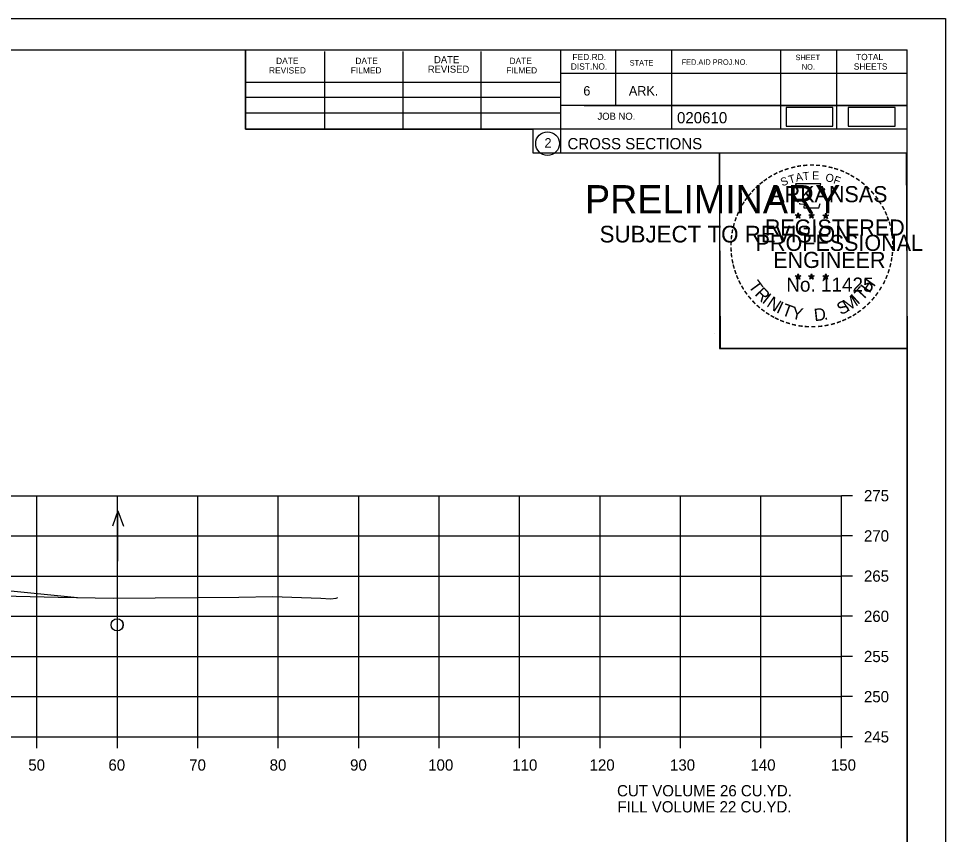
# Model space of a CAD drawing. Extents: x 1103485 to 1107180, y 2010593 to 2011873.
# Drawn here: x 1107064.9 to 1107180.1, y 2011131.3 to 2011232.8 of the extents above; entities that cross this region are included whole.
import ezdxf

# ---------------------------------------------------------------- set-up
doc = ezdxf.new("R2010")
doc.units = 0
for name, color, linetype in [('R_Axis', 7, 'Continuous'), ('R_Axis Annot', 7, 'Continuous'), ('R_Border', 7, 'Continuous'), ('R_Border PE', 7, 'Continuous'), ('R_Border Prem', 7, 'Continuous'), ('R_Drive', 7, 'Continuous'), ('R_Exist Surface', 7, 'Continuous'), ('R_Grid', 7, 'Continuous'), ('R_No Plot', 7, 'Continuous'), ('R_Water', 7, 'Continuous'), ('R_Water Annot', 7, 'Continuous')]:
    doc.layers.add(name, color=color, linetype=linetype)

msp = doc.modelspace()

# ---------------------------------------------------------------- linework, layer by layer
at = {"layer": 'R_Axis'}
for p, q in [((1107167.18, 2011143.49), (1107167.18, 2011173.49)), ((1107168.58, 2011173.49), (1107167.18, 2011173.49)), ((1107168.58, 2011168.49), (1107167.18, 2011168.49)), ((1107168.58, 2011163.49), (1107167.18, 2011163.49)), ((1107168.58, 2011158.49), (1107167.18, 2011158.49)), ((1107168.58, 2011153.49), (1107167.18, 2011153.49)), ((1107168.58, 2011148.49), (1107167.18, 2011148.49)), ((1106867.18, 2011143.49), (1107167.18, 2011143.49)), ((1107067.18, 2011142.09), (1107067.18, 2011143.49)), ((1107077.18, 2011142.09), (1107077.18, 2011143.49)), ((1107087.18, 2011142.09), (1107087.18, 2011143.49)), ((1107097.18, 2011142.09), (1107097.18, 2011143.49)), ((1107107.18, 2011142.09), (1107107.18, 2011143.49)), ((1107117.18, 2011142.09), (1107117.18, 2011143.49)), ((1107127.18, 2011142.09), (1107127.18, 2011143.49)), ((1107137.18, 2011142.09), (1107137.18, 2011143.49)), ((1107147.18, 2011142.09), (1107147.18, 2011143.49)), ((1107157.18, 2011142.09), (1107157.18, 2011143.49)), ((1107167.18, 2011142.09), (1107167.18, 2011143.49)), ((1107168.58, 2011143.49), (1107167.18, 2011143.49))]:
    msp.add_line(p, q, dxfattribs=at)
at = {"layer": 'R_Border'}
for p, q in [((1106859.18, 2011228.95), (1107175.36, 2011228.95)), ((1107093.1, 2011219.07), (1107093.1, 2011228.95)), ((1107102.96, 2011219.07), (1107102.96, 2011228.75)), ((1107112.72, 2011219.07), (1107112.72, 2011228.75)), ((1107122.4, 2011219.07), (1107122.4, 2011228.75)), ((1107132.26, 2011228.95), (1107132.26, 2011216.15)), ((1107139.1, 2011228.95), (1107139.1, 2011222.01)), ((1107146.04, 2011228.95), (1107146.04, 2011219.07)), ((1107159.62, 2011228.95), (1107159.62, 2011219.07)), ((1107166.56, 2011228.95), (1107166.56, 2011219.07)), ((1107175.36, 2011023.49), (1107175.36, 2011228.95)), ((1107175.36, 2011226.01), (1107132.26, 2011226.01)), ((1107175.36, 2011226.03), (1107175.36, 2011226.03)), ((1107093.1, 2011224.93), (1107132.26, 2011224.93)), ((1107093.1, 2011223.07), (1107132.26, 2011223.07)), ((1107175.36, 2011222.01), (1107132.26, 2011222.01)), ((1107135.22, 2011222.01), (1107175.36, 2011222.01)), ((1107093.1, 2011219.07), (1107093.1, 2011221.13)), ((1107093.1, 2011221.13), (1107132.26, 2011221.13)), ((1107175.36, 2011219.07), (1107093.1, 2011219.07)), ((1107132.26, 2011216.15), (1107175.36, 2011216.15))]:
    msp.add_line(p, q, dxfattribs=at)
msp.add_circle((1107130.65, 2011217.29), 1.47, dxfattribs=at)
at = {"layer": 'R_Border PE'}
for p, q in [((1107161.45, 2011208.41), (1107161.8, 2011208.3)), ((1107161.45, 2011208.41), (1107161.7, 2011208.36)), ((1107161.45, 2011208.41), (1107161.69, 2011208.29)), ((1107161.58, 2011208), (1107161.8, 2011208.3)), ((1107161.58, 2011208), (1107161.71, 2011208.24)), ((1107161.58, 2011208), (1107161.8, 2011208.22)), ((1107161.8, 2011208.66), (1107161.76, 2011208.41)), ((1107161.8, 2011208.3), (1107161.8, 2011208.66)), ((1107161.8, 2011208.66), (1107161.85, 2011208.41)), ((1107162.14, 2011208.41), (1107161.8, 2011208.3)), ((1107162.01, 2011208), (1107161.8, 2011208.3)), ((1107162.01, 2011208), (1107161.8, 2011208.21)), ((1107162.14, 2011208.41), (1107161.86, 2011208.36)), ((1107162.01, 2011208), (1107161.87, 2011208.29)), ((1107162.14, 2011208.41), (1107161.94, 2011208.31)), ((1107163.12, 2011208.41), (1107163.47, 2011208.3)), ((1107163.12, 2011208.41), (1107163.37, 2011208.36)), ((1107163.12, 2011208.41), (1107163.36, 2011208.29)), ((1107163.25, 2011208), (1107163.47, 2011208.3)), ((1107163.25, 2011208), (1107163.38, 2011208.24)), ((1107163.25, 2011208), (1107163.47, 2011208.22)), ((1107163.47, 2011208.66), (1107163.43, 2011208.41)), ((1107163.47, 2011208.3), (1107163.47, 2011208.66)), ((1107163.47, 2011208.66), (1107163.52, 2011208.41)), ((1107163.81, 2011208.41), (1107163.47, 2011208.3)), ((1107163.68, 2011208), (1107163.47, 2011208.3)), ((1107163.68, 2011208), (1107163.47, 2011208.21)), ((1107163.81, 2011208.41), (1107163.53, 2011208.36)), ((1107163.68, 2011208), (1107163.54, 2011208.29)), ((1107163.81, 2011208.41), (1107163.61, 2011208.31)), ((1107164.88, 2011208.4), (1107165.23, 2011208.28)), ((1107164.88, 2011208.4), (1107165.14, 2011208.35)), ((1107164.88, 2011208.4), (1107165.12, 2011208.27)), ((1107165.02, 2011207.99), (1107165.23, 2011208.28)), ((1107165.02, 2011207.99), (1107165.14, 2011208.23)), ((1107165.02, 2011207.99), (1107165.23, 2011208.2)), ((1107165.23, 2011208.65), (1107165.19, 2011208.4)), ((1107165.23, 2011208.28), (1107165.23, 2011208.65)), ((1107165.23, 2011208.65), (1107165.28, 2011208.4)), ((1107165.58, 2011208.4), (1107165.23, 2011208.28)), ((1107165.44, 2011207.99), (1107165.23, 2011208.28)), ((1107165.44, 2011207.99), (1107165.23, 2011208.2)), ((1107165.58, 2011208.4), (1107165.29, 2011208.35)), ((1107165.44, 2011207.99), (1107165.31, 2011208.28)), ((1107165.58, 2011208.4), (1107165.37, 2011208.29)), ((1107161.44, 2011200.83), (1107161.79, 2011200.72)), ((1107161.44, 2011200.83), (1107161.7, 2011200.79)), ((1107161.44, 2011200.83), (1107161.68, 2011200.71)), ((1107161.58, 2011200.43), (1107161.79, 2011200.72)), ((1107161.58, 2011200.43), (1107161.7, 2011200.67)), ((1107161.58, 2011200.43), (1107161.79, 2011200.64)), ((1107161.79, 2011201.09), (1107161.75, 2011200.84)), ((1107161.79, 2011200.72), (1107161.79, 2011201.09)), ((1107161.79, 2011201.09), (1107161.84, 2011200.84)), ((1107162.14, 2011200.83), (1107161.79, 2011200.72)), ((1107162.01, 2011200.43), (1107161.79, 2011200.72)), ((1107162.01, 2011200.43), (1107161.79, 2011200.64)), ((1107162.14, 2011200.83), (1107161.85, 2011200.79)), ((1107162.01, 2011200.43), (1107161.87, 2011200.72)), ((1107162.14, 2011200.83), (1107161.94, 2011200.73)), ((1107163.11, 2011200.83), (1107163.46, 2011200.72)), ((1107163.11, 2011200.83), (1107163.37, 2011200.79)), ((1107163.11, 2011200.83), (1107163.35, 2011200.71)), ((1107163.25, 2011200.43), (1107163.46, 2011200.72)), ((1107163.25, 2011200.43), (1107163.37, 2011200.67)), ((1107163.25, 2011200.43), (1107163.46, 2011200.64)), ((1107163.46, 2011201.09), (1107163.42, 2011200.84)), ((1107163.46, 2011200.72), (1107163.46, 2011201.09)), ((1107163.46, 2011201.09), (1107163.51, 2011200.84)), ((1107163.81, 2011200.83), (1107163.46, 2011200.72)), ((1107163.68, 2011200.43), (1107163.46, 2011200.72)), ((1107163.68, 2011200.43), (1107163.46, 2011200.64)), ((1107163.81, 2011200.83), (1107163.52, 2011200.79)), ((1107163.68, 2011200.43), (1107163.54, 2011200.72)), ((1107163.81, 2011200.83), (1107163.61, 2011200.73)), ((1107164.88, 2011200.82), (1107165.23, 2011200.71)), ((1107164.88, 2011200.82), (1107165.13, 2011200.78)), ((1107164.88, 2011200.82), (1107165.12, 2011200.7)), ((1107165.01, 2011200.42), (1107165.23, 2011200.71)), ((1107165.01, 2011200.42), (1107165.14, 2011200.66)), ((1107165.01, 2011200.42), (1107165.23, 2011200.63)), ((1107165.23, 2011201.08), (1107165.19, 2011200.83)), ((1107165.23, 2011200.71), (1107165.23, 2011201.08)), ((1107165.23, 2011201.08), (1107165.28, 2011200.83)), ((1107165.58, 2011200.82), (1107165.23, 2011200.71)), ((1107165.44, 2011200.42), (1107165.23, 2011200.71)), ((1107165.44, 2011200.42), (1107165.23, 2011200.63)), ((1107165.58, 2011200.82), (1107165.29, 2011200.78)), ((1107165.44, 2011200.42), (1107165.31, 2011200.71)), ((1107165.58, 2011200.82), (1107165.37, 2011200.72))]:
    msp.add_line(p, q, dxfattribs=at)
for points in [[(1107161.49, 2011212.29), (1107161.76, 2011211.46)], [(1107165, 2011211.36), (1107165.14, 2011211.65), (1107164.46, 2011211.62), (1107164.61, 2011212.29), (1107161.49, 2011212.29)], [(1107161.98, 2011209.86), (1107161.98, 2011209.78), (1107162.54, 2011209.76), (1107162.49, 2011209.28), (1107164.36, 2011209.28), (1107164.56, 2011209.82)], [(1107161.8, 2011208.66), (1107162.01, 2011208), (1107161.45, 2011208.41), (1107162.14, 2011208.41), (1107161.58, 2011208), (1107161.8, 2011208.66)], [(1107163.47, 2011208.66), (1107163.68, 2011208), (1107163.12, 2011208.41), (1107163.81, 2011208.41), (1107163.25, 2011208), (1107163.47, 2011208.66)], [(1107165.23, 2011208.65), (1107165.44, 2011207.99), (1107164.88, 2011208.4), (1107165.58, 2011208.4), (1107165.02, 2011207.99), (1107165.23, 2011208.65)], [(1107161.79, 2011201.09), (1107162.01, 2011200.43), (1107161.44, 2011200.83), (1107162.14, 2011200.83), (1107161.58, 2011200.43), (1107161.79, 2011201.09)], [(1107163.46, 2011201.09), (1107163.68, 2011200.43), (1107163.11, 2011200.83), (1107163.81, 2011200.83), (1107163.25, 2011200.43), (1107163.46, 2011201.09)], [(1107165.23, 2011201.08), (1107165.44, 2011200.42), (1107164.88, 2011200.82), (1107165.58, 2011200.82), (1107165.01, 2011200.42), (1107165.23, 2011201.08)]]:
    msp.add_lwpolyline(points, dxfattribs=at)
for centre, radius in [((1107161.8, 2011208.3), 0.172), ((1107161.8, 2011208.3), 0.145), ((1107161.8, 2011208.3), 0.116), ((1107161.8, 2011208.3), 0.0991), ((1107161.8, 2011208.3), 0.0747), ((1107161.8, 2011208.3), 0.0495), ((1107161.8, 2011208.3), 0.0296), ((1107163.47, 2011208.3), 0.172), ((1107163.47, 2011208.3), 0.145), ((1107163.47, 2011208.3), 0.116), ((1107163.47, 2011208.3), 0.0991), ((1107163.47, 2011208.3), 0.0747), ((1107163.47, 2011208.3), 0.0495), ((1107163.47, 2011208.3), 0.0296), ((1107165.23, 2011208.28), 0.172), ((1107165.23, 2011208.28), 0.145), ((1107165.23, 2011208.28), 0.116), ((1107165.23, 2011208.28), 0.0991), ((1107165.23, 2011208.28), 0.0747), ((1107165.23, 2011208.28), 0.0495), ((1107165.23, 2011208.28), 0.0296), ((1107161.79, 2011200.72), 0.172), ((1107161.79, 2011200.72), 0.145), ((1107161.79, 2011200.72), 0.116), ((1107161.79, 2011200.72), 0.0991), ((1107161.79, 2011200.72), 0.0747), ((1107161.79, 2011200.72), 0.0495), ((1107161.79, 2011200.72), 0.0296), ((1107163.46, 2011200.72), 0.172), ((1107163.46, 2011200.72), 0.145), ((1107163.46, 2011200.72), 0.116), ((1107163.46, 2011200.72), 0.0991), ((1107163.46, 2011200.72), 0.0747), ((1107163.46, 2011200.72), 0.0495), ((1107163.46, 2011200.72), 0.0296), ((1107165.23, 2011200.71), 0.172), ((1107165.23, 2011200.71), 0.145), ((1107165.23, 2011200.71), 0.116), ((1107165.23, 2011200.71), 0.0991), ((1107165.23, 2011200.71), 0.0747), ((1107165.23, 2011200.71), 0.0495), ((1107165.23, 2011200.71), 0.0296)]:
    msp.add_circle(centre, radius, dxfattribs=at)
at = {"layer": 'R_Drive'}
msp.add_line((1107048.15, 2011163.24), (1107072.23, 2011160.83), dxfattribs=at)
at = {"layer": 'R_Exist Surface'}
msp.add_lwpolyline([(1107061.07, 2011161.07), (1107069.8, 2011160.88), (1107076.69, 2011160.74), (1107092.27, 2011160.88), (1107096.46, 2011160.97), (1107102.47, 2011160.74), (1107103.68, 2011160.68), (1107104.37, 2011160.73), (1107104.56, 2011160.83)], dxfattribs=at)
at = {"layer": 'R_Grid'}
for p, q in [((1106867.18, 2011173.49), (1107167.18, 2011173.49)), ((1107067.18, 2011143.49), (1107067.18, 2011173.49)), ((1107077.18, 2011143.49), (1107077.18, 2011173.49)), ((1107087.18, 2011143.49), (1107087.18, 2011173.49)), ((1107097.18, 2011143.49), (1107097.18, 2011173.49)), ((1107107.18, 2011143.49), (1107107.18, 2011173.49)), ((1107117.18, 2011143.49), (1107117.18, 2011173.49)), ((1107127.18, 2011143.49), (1107127.18, 2011173.49)), ((1107137.18, 2011143.49), (1107137.18, 2011173.49)), ((1107147.18, 2011143.49), (1107147.18, 2011173.49)), ((1107157.18, 2011143.49), (1107157.18, 2011173.49)), ((1107167.18, 2011143.49), (1107167.18, 2011173.49)), ((1106867.18, 2011168.49), (1107167.18, 2011168.49)), ((1106867.18, 2011163.49), (1107167.18, 2011163.49)), ((1106867.18, 2011158.49), (1107167.18, 2011158.49)), ((1106867.18, 2011153.49), (1107167.18, 2011153.49)), ((1106867.18, 2011148.49), (1107167.18, 2011148.49)), ((1106867.18, 2011143.49), (1107167.18, 2011143.49))]:
    msp.add_line(p, q, dxfattribs=at)
at = {"layer": 'R_No Plot'}
for p, q in [((1106846.78, 2011232.85), (1107180.12, 2011232.85)), ((1107151.4, 2011193.7), (1107151.4, 2011193.7))]:
    msp.add_line(p, q, dxfattribs=at)
for points in [[(1106846.78, 2011232.85), (1107180.12, 2011232.85), (1107180.12, 2011019.51), (1106846.78, 2011019.51)], [(1107093.1, 2011228.95), (1107093.1, 2011219.07), (1107128.84, 2011219.07), (1107128.84, 2011216.15), (1107152.04, 2011216.15), (1107152.04, 2011191.82), (1107175.36, 2011191.82), (1107175.36, 2011023.49), (1106859.18, 2011023.49), (1106859.18, 2011228.95)], [(1107152.04, 2011216.15), (1107175.24, 2011216.15), (1107175.36, 2011191.82), (1107152.16, 2011191.82)]]:
    msp.add_lwpolyline(points, close=True, dxfattribs=at)
at = {"layer": 'R_Water'}
for points in [[(1107160.3, 2011219.47), (1107166.13, 2011219.47), (1107166.13, 2011221.78), (1107160.3, 2011221.78)], [(1107168.04, 2011219.45), (1107173.87, 2011219.45), (1107173.87, 2011221.76), (1107168.04, 2011221.76)]]:
    msp.add_lwpolyline(points, close=True, dxfattribs=at)
for radius in [0.755, 0.75]:
    msp.add_circle((1107077.14, 2011157.42), radius, dxfattribs=at)
at = {"layer": 'R_Water Annot'}
for p, q in [((1107077.25, 2011171.61), (1107076.55, 2011169.69)), ((1107077.25, 2011165.33), (1107077.25, 2011171.61)), ((1107077.25, 2011171.61), (1107077.95, 2011169.69))]:
    msp.add_line(p, q, dxfattribs=at)

# ---------------------------------------------------------------- texts
at = {"layer": 'R_Axis Annot'}
for s, p in [('275', (1107169.98, 2011172.79)), ('270', (1107169.98, 2011167.79)), ('265', (1107169.98, 2011162.79)), ('260', (1107169.98, 2011157.79)), ('255', (1107169.98, 2011152.79)), ('250', (1107169.98, 2011147.79)), ('245', (1107169.98, 2011142.79)), ('50', (1107066.1, 2011139.29)), ('60', (1107076.06, 2011139.29)), ('70', (1107086.1, 2011139.29)), ('80', (1107096.1, 2011139.29)), ('90', (1107106.1, 2011139.29)), ('100', (1107115.81, 2011139.29)), ('110', (1107126.26, 2011139.29)), ('120', (1107135.87, 2011139.29)), ('130', (1107145.87, 2011139.29)), ('140', (1107155.87, 2011139.29)), ('150', (1107165.87, 2011139.29)), ('CUT VOLUME 26 CU.YD.', (1107139.29, 2011136.09)), ('FILL VOLUME 22 CU.YD.', (1107139.34, 2011134.09))]:
    msp.add_text(s, height=1.4, dxfattribs=at).set_placement(p)
at = {"layer": 'R_Border'}
for s, height, p in [('FED.RD.', 0.782, (1107133.74, 2011227.67)), ('SHEET', 0.684, (1107161.48, 2011227.67)), ('TOTAL', 0.782, (1107169, 2011227.67)), ('DATE', 0.782, (1107096.9, 2011227.19)), ('DATE', 0.782, (1107106.76, 2011227.19)), ('DATE', 0.879, (1107116.54, 2011227.29)), ('DATE', 0.782, (1107125.92, 2011227.19)), ('DIST.NO.', 0.782, (1107133.54, 2011226.49)), ('STATE', 0.684, (1107140.86, 2011226.99)), ('FED.AID PROJ.NO.', 0.684, (1107147.32, 2011227.09)), ('NO.', 0.684, (1107162.26, 2011226.49)), ('SHEETS', 0.782, (1107168.72, 2011226.49)), ('REVISED', 0.782, (1107096.02, 2011226.01)), ('FILMED', 0.782, (1107106.18, 2011226.01)), ('REVISED', 0.879, (1107115.76, 2011226.11)), ('FILMED', 0.782, (1107125.52, 2011226.01)), ('6', 1.17, (1107135.1, 2011223.27)), ('ARK.', 1.172, (1107140.76, 2011223.27)), ('JOB NO.', 0.879, (1107136.86, 2011220.25)), ('020610', 1.4, (1107146.74, 2011219.81)), ('2', 1.17, (1107130.27, 2011216.8)), ('CROSS SECTIONS', 1.4, (1107133.13, 2011216.58))]:
    msp.add_text(s, height=height, rotation=360, dxfattribs=at).set_placement(p)
at = {"layer": 'R_Border PE'}
for s, height, rotation, p in [('-', 1.6, 13.6301, (1107160.99, 2011213.65)), ('-', 1.6, 10.2193, (1107161.67, 2011213.82)), ('-', 1.6, 5.8968, (1107162.39, 2011213.93)), ('-', 1.6, 0.1862, (1107163.17, 2011214)), ('-', 1.6, 357.743, (1107163.89, 2011213.98)), ('-', 1.6, 352.1617, (1107164.63, 2011213.93)), ('-', 1.6, 347.2049, (1107165.35, 2011213.81)), ('-', 1.6, 34.0636, (1107158.37, 2011212.46)), ('-', 1.6, 28.7918, (1107158.97, 2011212.83)), ('-', 1.6, 24.3072, (1107159.6, 2011213.14)), ('-', 1.6, 19.1761, (1107160.24, 2011213.41)), ('T', 1, 16.4036, (1107160.76, 2011212.29)), ('A', 1, 11.2132, (1107161.58, 2011212.55)), ('T', 1, 6.0228, (1107162.43, 2011212.71)), ('E', 1, 0.8323, (1107163.54, 2011212.82)), ('O', 1, 350.4515, (1107165.14, 2011212.61)), ('-', 1.6, 342.3362, (1107165.99, 2011213.66)), ('-', 1.6, 337.8551, (1107166.72, 2011213.44)), ('-', 1.6, 334.1211, (1107167.35, 2011213.17)), ('-', 1.6, 329.6409, (1107167.93, 2011212.88)), ('-', 1.6, 42.9622, (1107156.89, 2011211.27)), ('-', 1.6, 38.9507, (1107157.32, 2011211.68)), ('-', 1.6, 36.2317, (1107157.8, 2011212.06)), ('S', 1, 21.594, (1107159.84, 2011211.96)), ('F', 1, 340.0707, (1107166.1, 2011212.38)), ('-', 1.6, 325.8627, (1107168.58, 2011212.52)), ('-', 1.6, 320.5297, (1107169.19, 2011212.1)), ('-', 1.6, 50.6142, (1107156.04, 2011210.3)), ('-', 1.6, 48.423, (1107156.44, 2011210.79)), ('ARKANSAS', 2, 360, (1107158.34, 2011210)), ('-', 1.6, 315.5786, (1107169.78, 2011211.61)), ('-', 1.6, 309.8797, (1107170.35, 2011211.06)), ('-', 1.6, 58.0706, (1107155.3, 2011209.21)), ('-', 1.6, 54.2325, (1107155.62, 2011209.74)), ('-', 1.6, 306.6522, (1107170.88, 2011210.46)), ('-', 1.4, 303.6753, (1107171.36, 2011209.89)), ('-', 1.6, 67.7743, (1107154.73, 2011207.98)), ('-', 1.6, 62.8713, (1107154.98, 2011208.59)), ('-', 1.6, 299.6684, (1107171.68, 2011209.28)), ('-', 1.6, 294.6628, (1107172.01, 2011208.67)), ('-', 1.6, 72.3945, (1107154.51, 2011207.35)), ('REGISTERED', 2, 360, (1107157.66, 2011205.85)), ('DWB', 0.01, 360, (1107161.78, 2011208.29)), ('DWB', 0.01, 360, (1107163.45, 2011208.29)), ('DWB', 0.01, 360, (1107165.22, 2011208.28)), ('-', 1.6, 290.5728, (1107172.26, 2011208.09)), ('-', 1.6, 285.1233, (1107172.5, 2011207.51)), ('-', 1.6, 81.2013, (1107154.18, 2011205.93)), ('-', 1.6, 75.461, (1107154.31, 2011206.64)), ('-', 1.6, 280.5493, (1107172.7, 2011206.77)), ('-', 1.6, 85.1863, (1107154.1, 2011205.24)), ('PROFESSIONAL', 2, 360, (1107156.52, 2011203.94)), ('-', 1.6, 276.5962, (1107172.86, 2011206)), ('-', 1.6, 274.3301, (1107172.92, 2011205.28)), ('-', 1.6, 94.1959, (1107154.11, 2011203.81)), ('-', 1.6, 89.0622, (1107154.08, 2011204.53)), ('-', 1.6, 269.9407, (1107172.95, 2011204.65)), ('-', 1.6, 98.9479, (1107154.18, 2011203.14)), ('ENGINEER', 2, 360, (1107158.7, 2011201.82)), ('-', 1.6, 260.9953, (1107172.86, 2011203.33)), ('-', 1.6, 263.5172, (1107172.94, 2011203.98)), ('-', 1.6, 101.7149, (1107154.32, 2011202.41)), ('-', 1.6, 105.4578, (1107154.48, 2011201.81)), ('-', 1.6, 255.7626, (1107172.75, 2011202.65)), ('-', 1.6, 109.0874, (1107154.7, 2011201.18)), ('-', 1.6, 114.0643, (1107154.95, 2011200.59)), ('No. 11425', 1.757, 360, (1107160.33, 2011198.87)), ('DWB', 0.01, 360, (1107161.78, 2011200.72)), ('DWB', 0.01, 360, (1107163.45, 2011200.72)), ('DWB', 0.01, 360, (1107165.22, 2011200.71)), ('-', 1.6, 247.8887, (1107172.35, 2011201.26)), ('-', 1.6, 252.8681, (1107172.57, 2011201.93)), ('-', 1.6, 115.7289, (1107155.25, 2011199.97)), ('-', 1.6, 120.4471, (1107155.61, 2011199.38)), ('T', 1.54, 306.0406, (1107155.55, 2011199.56)), ('T', 1.54, 46.6444, (1107169.78, 2011197.65)), ('H', 1.54, 54.6088, (1107170.67, 2011198.6)), ('-', 1.6, 239.0712, (1107171.69, 2011199.88)), ('-', 1.6, 244.6197, (1107172.09, 2011200.63)), ('-', 1.6, 125.8934, (1107156.01, 2011198.82)), ('-', 1.6, 130.7181, (1107156.48, 2011198.27)), ('R', 1.54, 314.005, (1107156.32, 2011198.51)), ('I', 1.54, 321.9694, (1107157.22, 2011197.58)), ('M', 1.54, 32.6563, (1107167.94, 2011196.33)), ('I', 1.54, 42.1136, (1107169.22, 2011197.18)), ('-', 1.6, 233.8452, (1107171.29, 2011199.22)), ('-', 1.6, 134.2238, (1107156.99, 2011197.73)), ('-', 1.6, 138.9338, (1107157.52, 2011197.26)), ('N', 1.54, 326.5002, (1107157.78, 2011197.11)), ('I', 1.54, 335.3603, (1107158.99, 2011196.32)), ('T', 1.54, 339.8912, (1107159.65, 2011196)), ('S', 1.54, 26.9312, (1107167.1, 2011195.92)), ('-', 1.6, 225.7653, (1107170.38, 2011198.09)), ('-', 1.6, 231.2538, (1107170.86, 2011198.66)), ('-', 1.6, 144.6463, (1107158.07, 2011196.86)), ('-', 1.6, 148.0898, (1107158.64, 2011196.48)), ('Y', 1.54, 347.8556, (1107160.87, 2011195.55)), ('D', 1.54, 6.3969, (1107163.85, 2011195.19)), ('-', 1.6, 212.2491, (1107168.78, 2011196.72)), ('-', 1.6, 215.7363, (1107169.31, 2011197.11)), ('-', 1.6, 221.0851, (1107169.86, 2011197.58)), ('-', 1.6, 151.5704, (1107159.21, 2011196.16)), ('-', 1.6, 154.6002, (1107159.74, 2011195.91)), ('-', 1.6, 158.5612, (1107160.36, 2011195.66)), ('-', 1.6, 162.7983, (1107161.05, 2011195.45)), ('-', 1.6, 167.5555, (1107161.76, 2011195.28)), ('.', 1.54, 13.7642, (1107165.05, 2011195.32)), ('-', 1.6, 195.4743, (1107166.3, 2011195.54)), ('-', 1.6, 200.7184, (1107166.98, 2011195.79)), ('-', 1.6, 204.2516, (1107167.6, 2011196.06)), ('-', 1.6, 207.3568, (1107168.22, 2011196.38)), ('-', 1.6, 173.1155, (1107162.53, 2011195.17)), ('-', 1.6, 176.5183, (1107163.28, 2011195.12)), ('-', 1.6, 181.5918, (1107164.03, 2011195.14)), ('-', 1.6, 185.8167, (1107164.84, 2011195.21)), ('-', 1.6, 191.2858, (1107165.57, 2011195.35))]:
    msp.add_text(s, height=height, rotation=rotation, dxfattribs=at).set_placement(p)
at = {"layer": 'R_Border Prem'}
for s, height, p in [('PRELIMINARY', 3.5, (1107135.31, 2011208.62)), ('DWB', 0.01, (1107136.06, 2011210.46)), ('SUBJECT TO REVISION', 2.0751, (1107137.12, 2011204.99))]:
    msp.add_text(s, height=height, rotation=360, dxfattribs=at).set_placement(p)

doc.saveas('drawing.dxf')
